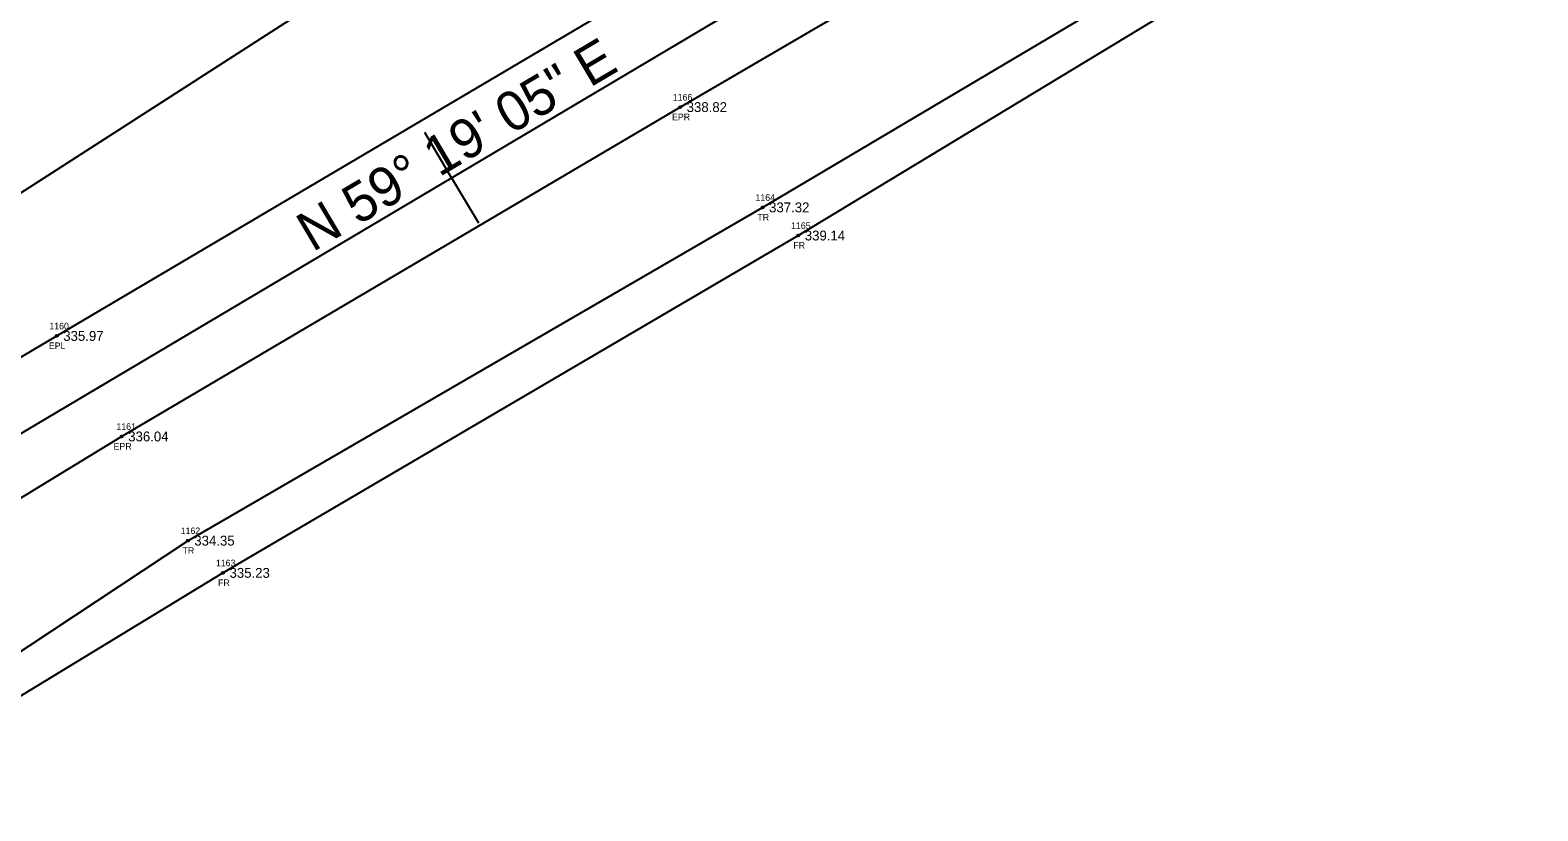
# Model space of a CAD drawing. Extents: x 2231119 to 2232595, y 1035731 to 1037094.
# Drawn here: x 2231847.5 to 2232076.9, y 1036547.7 to 1036666.5 of the extents above; entities that cross this region are included whole.
import ezdxf

# ---------------------------------------------------------------- set-up
doc = ezdxf.new("R2010")
doc.units = 0
for name, color, linetype in [('RD_EX_Fence_Other', 7, 'Continuous'), ('RD_EX_Fence_Other_txCode', 7, 'Continuous'), ('RD_EX_Road', 7, 'Continuous'), ('RD_EX_Road_txCode', 7, 'Continuous'), ('RD_EX_TX_Fence_Other_ELEV', 7, 'Continuous'), ('RD_EX_TX_Road_ELEV', 7, 'Continuous'), ('RD_EX_TX_VEG_ELEV', 7, 'Continuous'), ('RD_EX_VEG', 7, 'Continuous'), ('RD_EX_VEG_txCode', 7, 'Continuous'), ('RD_HC_Cl', 7, 'Continuous'), ('RD_HC_Data', 7, 'Continuous'), ('RD_HC_Data_Tic', 7, 'Continuous'), ('RD_SMD_Locator', 7, 'Continuous')]:
    doc.layers.add(name, color=color, linetype=linetype)

msp = doc.modelspace()

# ---------------------------------------------------------------- linework, layer by layer
at = {"layer": 'RD_EX_Fence_Other'}
msp.add_lwpolyline([(2231742.82, 1036485.51), (2231730.99, 1036494.96), (2231789.88, 1036531.02), (2231876.81, 1036583.89), (2231964.37, 1036635.23), (2232046.18, 1036684.79), (2232133.57, 1036734.4), (2232210.6, 1036793.49), (2232301.78, 1036835.03)], dxfattribs=at)
at = {"layer": 'RD_EX_Road'}
for points in [[(2231606.1, 1036462.92), (2231601.27, 1036470.82), (2231681.58, 1036519.84), (2231764.99, 1036568.78), (2231851.5, 1036619.95), (2231935.62, 1036669.65), (2232021.78, 1036720.22), (2232106.75, 1036770.57), (2232190.54, 1036819.2), (2232275.92, 1036870.27)], [(2231606.1, 1036462.92), (2231610.57, 1036455.36), (2231692.09, 1036503.24), (2231706.07, 1036512.59), (2231777.1, 1036553.27), (2231861.39, 1036604.65), (2231946.39, 1036654.77), (2232031.07, 1036704.2), (2232117.06, 1036755.16), (2232199.91, 1036803.8), (2232286.7, 1036855.36)]]:
    msp.add_lwpolyline(points, dxfattribs=at)
at = {"layer": 'RD_EX_VEG'}
for points in [[(2231598.25, 1036478.35), (2231674.54, 1036527.95), (2231759.25, 1036584.63), (2231839.99, 1036637.88), (2231924.53, 1036692.24), (2232004.98, 1036742.14), (2232090.99, 1036793.16), (2232172.16, 1036843), (2232262.27, 1036890.61)], [(2231753.59, 1036474.98), (2231730.55, 1036496.34), (2231788.45, 1036533.87), (2231871.45, 1036588.79), (2231958.94, 1036639.51), (2232040.64, 1036687.92), (2232130.59, 1036740.48), (2232213.07, 1036784.39), (2232299.54, 1036835.55)]]:
    msp.add_lwpolyline(points, dxfattribs=at)
at = {"layer": 'RD_HC_Cl'}
msp.add_line((2231548.98, 1036428.87), (2232281.06, 1036863.23), dxfattribs=at)
at = {"layer": 'RD_HC_Data_Tic'}
for q in [(2231907.52, 1036650.9), (2231915.68, 1036637.14)]:
    msp.add_line((2231911.6, 1036644.02), q, dxfattribs=at)
at = {"layer": 'RD_SMD_Locator'}
for centre in [(2231946.39, 1036654.77), (2231958.94, 1036639.51), (2231964.37, 1036635.23), (2231851.5, 1036619.95), (2231861.39, 1036604.65), (2231871.45, 1036588.79), (2231876.81, 1036583.89)]:
    msp.add_circle(centre, 0.15, dxfattribs=at)

# ---------------------------------------------------------------- texts
at = {"layer": 'RD_EX_Fence_Other_txCode'}
for s, p in [('1165', (2231963.28, 1036636.23)), ('FR', (2231963.62, 1036633.23)), ('1163', (2231875.73, 1036584.89)), ('FR', (2231876.06, 1036581.89))]:
    msp.add_text(s, height=1, dxfattribs=at).set_placement(p)
at = {"layer": 'RD_EX_Road_txCode'}
for s, p in [('1166', (2231945.28, 1036655.77)), ('EPR', (2231945.16, 1036652.77)), ('1160', (2231850.38, 1036620.95)), ('EPL', (2231850.3, 1036617.95)), ('1161', (2231860.59, 1036605.65)), ('EPR', (2231860.16, 1036602.65))]:
    msp.add_text(s, height=1, dxfattribs=at).set_placement(p)
at = {"layer": 'RD_EX_TX_Fence_Other_ELEV'}
for s, p in [('339.14', (2231965.37, 1036634.48)), ('335.23', (2231877.81, 1036583.14))]:
    msp.add_text(s, height=1.5, dxfattribs=at).set_placement(p)
at = {"layer": 'RD_EX_TX_Road_ELEV'}
for s, p in [('338.82', (2231947.39, 1036654.02)), ('335.97', (2231852.5, 1036619.2)), ('336.04', (2231862.39, 1036603.9))]:
    msp.add_text(s, height=1.5, dxfattribs=at).set_placement(p)
at = {"layer": 'RD_EX_TX_VEG_ELEV'}
for s, p in [('337.32', (2231959.94, 1036638.76)), ('334.35', (2231872.45, 1036588.04))]:
    msp.add_text(s, height=1.5, dxfattribs=at).set_placement(p)
at = {"layer": 'RD_EX_VEG_txCode'}
for s, p in [('1164', (2231957.86, 1036640.51)), ('TR', (2231958.15, 1036637.51)), ('1162', (2231870.37, 1036589.79)), ('TR', (2231870.66, 1036586.79))]:
    msp.add_text(s, height=1, dxfattribs=at).set_placement(p)
at = {"layer": 'RD_HC_Data'}
msp.add_text('N 59%%d 19\' 05" E', height=6, rotation=30.682, dxfattribs=at).set_placement((2231890.45, 1036632.64))

doc.saveas('drawing.dxf')
